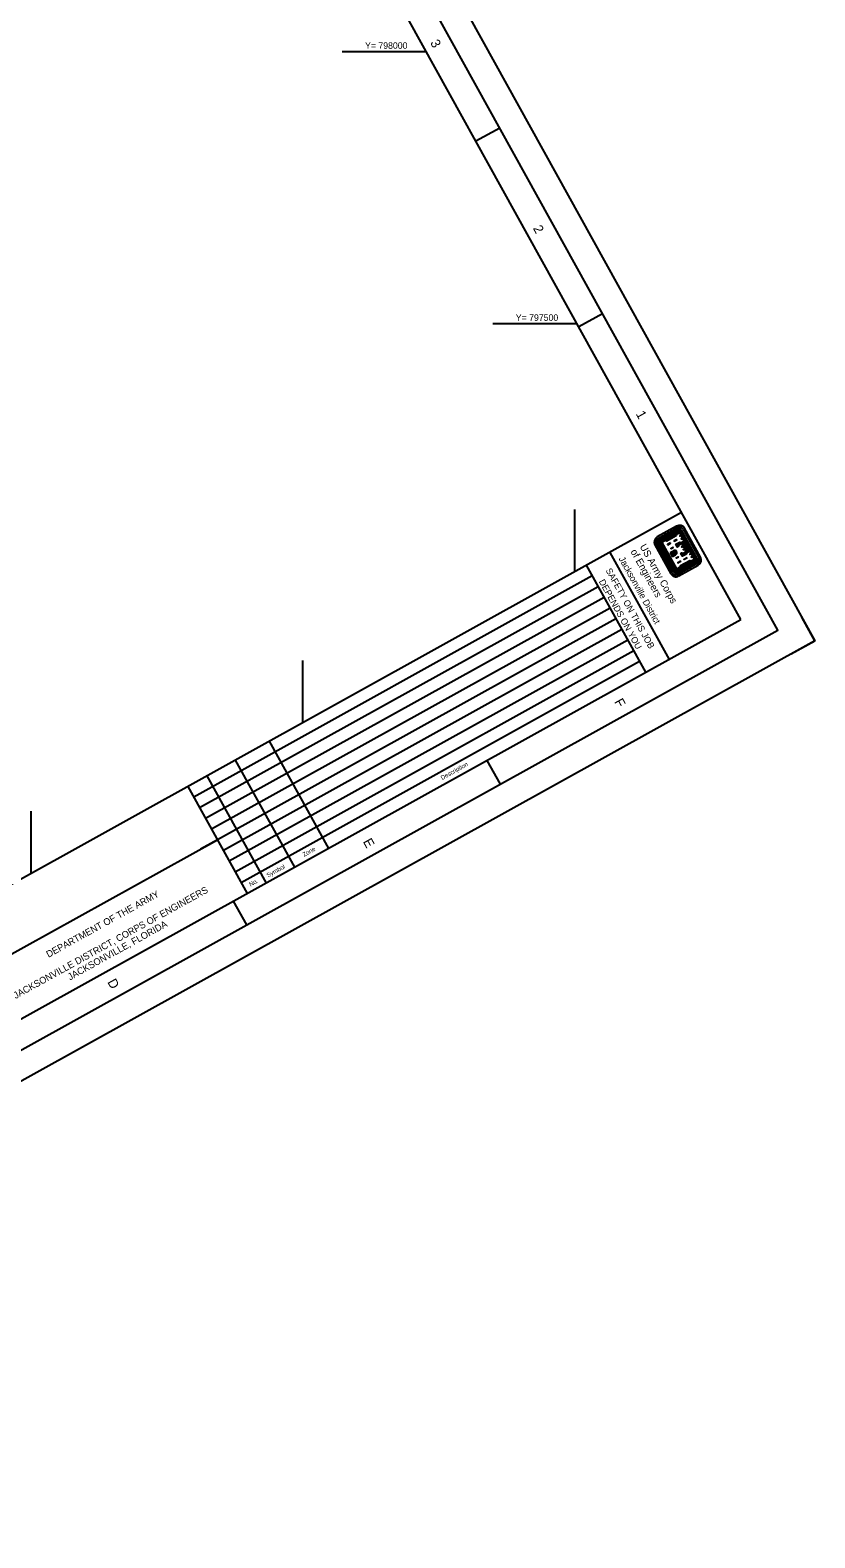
# Model space of a CAD drawing. Extents: x 602834 to 607941, y 795268 to 800765.
# Drawn here: x 606498 to 607941, y 795269 to 798039 of the extents above; entities that cross this region are included whole.
import ezdxf

# ---------------------------------------------------------------- set-up
doc = ezdxf.new("R2010")
doc.units = 0
for name, color, linetype in [('G-ANNO-NPLT', 7, 'Continuous'), ('G-ANNO-TEXT-LOGO', 7, 'Continuous'), ('G-ANNO-TEXT-TTLB', 7, 'Continuous'), ('G-ANNO-TTLB', 7, 'Continuous'), ('V-TOPO-COOR-STAT', 7, 'Continuous')]:
    doc.layers.add(name, color=color, linetype=linetype)

msp = doc.modelspace()

# ---------------------------------------------------------------- linework, layer by layer
at = {"layer": 'G-ANNO-NPLT'}
msp.add_lwpolyline([(605807.9, 800765.3), (607941.3, 796917.1), (604967.7, 795268.6), (602834.3, 799116.7)], close=True, dxfattribs=at)
msp.add_lwpolyline([(607897.6, 796892.9), (607941.3, 796917.1), (607917.1, 796960.8)], dxfattribs=at)
at = {"layer": 'G-ANNO-TEXT-LOGO'}
for p, q in [((607687.1, 797127.9), (607651.2, 797108.1)), ((607652.8, 797105.3), (607688.7, 797125.1)), ((607690.4, 797122.1), (607654.5, 797102.2)), ((607690.8, 797121.3), (607654.9, 797101.4)), ((607691.2, 797120.6), (607655.3, 797100.7)), ((607691.6, 797119.8), (607655.8, 797099.9)), ((607692.1, 797119), (607656.2, 797099.1)), ((607692.5, 797118.2), (607656.9, 797098.5)), ((607692.9, 797117.5), (607658.1, 797098.2)), ((607685.6, 797112.7), (607667.2, 797102.5)), ((607685.3, 797111.5), (607668.6, 797102.2)), ((607722.3, 797065.7), (607692.8, 797118.9)), ((607723.1, 797066.1), (607693.6, 797119.3)), ((607723.8, 797066.5), (607694.3, 797119.7)), ((607724.6, 797067), (607695.1, 797120.1)), ((607725.4, 797067.4), (607695.9, 797120.6)), ((607698.9, 797122.2), (607728.3, 797069.1)), ((607731.1, 797070.6), (607701.7, 797123.8)), ((607647, 797093.5), (607676.5, 797040.3)), ((607679.4, 797041.9), (607649.9, 797095.1)), ((607682.4, 797043.6), (607652.9, 797096.8)), ((607683.1, 797044), (607653.6, 797097.2)), ((607683.9, 797044.4), (607654.4, 797097.6)), ((607684.7, 797044.9), (607655.2, 797098)), ((607685.4, 797045.2), (607655.9, 797098.4)), ((607686, 797046), (607656.9, 797098.5)), ((607686.4, 797047.2), (607658.1, 797098.2)), ((607697.8, 797097.5), (607706.8, 797081.3)), ((607698.6, 797098), (607707.6, 797081.7)), ((607699.3, 797098.3), (607708.3, 797082.1)), ((607700.1, 797098.8), (607709.1, 797082.5)), ((607700.9, 797099.2), (607709.9, 797082.9)), ((607701.6, 797099.6), (607710.6, 797083.3)), ((607702.3, 797100), (607711.4, 797083.8)), ((607675.4, 797079.1), (607681.3, 797082.3)), ((607675.4, 797079.1), (607679.3, 797072.1)), ((607675.8, 797078.4), (607681.7, 797081.6)), ((607676.3, 797077.6), (607682.1, 797080.8)), ((607676.7, 797076.8), (607682.6, 797080)), ((607677.1, 797076.1), (607683, 797079.3)), ((607677.7, 797075), (607683.5, 797078.3)), ((607678.1, 797074.3), (607683.9, 797077.6)), ((607678.5, 797073.6), (607684.4, 797076.8)), ((607678.9, 797072.8), (607684.8, 797076)), ((607679.3, 797072.1), (607685.2, 797075.3)), ((607721.6, 797065.8), (607686, 797046)), ((607722, 797065), (607686.2, 797045.1)), ((607721.2, 797066.5), (607686.4, 797047.2)), ((607722.5, 797064.2), (607686.6, 797044.3)), ((607722.8, 797063.5), (607687, 797043.6)), ((607723.3, 797062.7), (607687.4, 797042.8)), ((607723.7, 797061.9), (607687.9, 797042)), ((607725.4, 797058.9), (607689.5, 797039.1)), ((607691.1, 797036.2), (607727, 797056.1)), ((607713.2, 797062.8), (607695, 797052.7)), ((607712, 797063.2), (607695.3, 797053.9))]:
    msp.add_line(p, q, dxfattribs=at)
for points in [[(607693.2, 797116.9), (607686.3, 797113.1), (607685.6, 797110.8), (607668.9, 797101.5), (607666.5, 797102.1), (607658.9, 797097.9), (607686.6, 797048.1), (607694.2, 797052.3), (607694.9, 797054.7), (607711.6, 797064), (607713.9, 797063.2), (607720.9, 797067.1), (607717.2, 797073.6), (607714.4, 797078.7), (607711.8, 797083.4), (607704.9, 797079.6), (607704.3, 797077.1), (607698.2, 797073.7), (607696.2, 797077.4), (607696.8, 797077.7), (607699.2, 797077), (607706, 797080.8), (607702.4, 797087.4), (607699.6, 797092.4), (607697, 797097.1), (607690.2, 797093.3), (607689.5, 797090.9), (607688.9, 797090.5), (607686.8, 797094.2), (607693, 797097.6), (607695.3, 797096.8), (607702.2, 797100.7), (607698.6, 797107.2), (607695.8, 797112.3), (607693.2, 797116.9)], [(607692.8, 797115.8), (607687, 797112.6), (607686.3, 797110.1), (607669, 797100.5), (607666.6, 797101.2), (607660.1, 797097.7), (607687, 797049.2), (607693.4, 797052.8), (607694.1, 797055.3), (607711.4, 797064.9), (607713.9, 797064.1), (607719.7, 797067.3), (607717.1, 797072.1), (607714.3, 797070.6), (607714.1, 797071), (607716.8, 797072.5), (607714.2, 797077.1), (607711.5, 797075.6), (607711.3, 797076), (607714.1, 797077.5), (607711.4, 797082.2), (607705.7, 797079), (607705, 797076.6), (607697.9, 797072.6), (607695.1, 797077.7), (607696.7, 797078.6), (607699.2, 797077.9), (607704.9, 797081.1), (607702.3, 797085.8), (607699.6, 797084.3), (607699.4, 797084.7), (607702.1, 797086.2), (607699.5, 797090.9), (607696.8, 797089.4), (607696.6, 797089.9), (607699.3, 797091.4), (607696.7, 797096), (607690.9, 797092.8), (607690.2, 797090.3), (607688.6, 797089.4), (607685.8, 797094.5), (607692.8, 797098.4), (607695.3, 797097.7), (607701.1, 797100.9), (607698.5, 797105.6), (607695.8, 797104.1), (607695.5, 797104.5), (607698.2, 797106), (607695.6, 797110.7), (607692.9, 797109.2), (607692.7, 797109.6), (607695.4, 797111.1), (607692.8, 797115.8)], [(607675.8, 797097), (607670.6, 797094.1), (607670.9, 797093.6), (607676.1, 797096.5), (607675.8, 797097)], [(607680.3, 797088.9), (607676.7, 797086.9), (607676.9, 797086.5), (607680.5, 797088.5), (607680.3, 797088.9)], [(607687.4, 797103.4), (607682.4, 797100.6), (607682.7, 797100.1), (607687.7, 797102.9), (607687.4, 797103.4)], [(607693.7, 797096.4), (607693.1, 797096.6), (607688.1, 797093.8), (607689, 797092.2), (607689.5, 797093.9), (607693.9, 797096.4)], [(607690.3, 797070.9), (607686.7, 797068.9), (607686.4, 797069.4), (607690, 797071.4), (607690.3, 797070.9)], [(607694.7, 797063), (607689.5, 797060.1), (607689.3, 797060.5), (607694.4, 797063.4), (607694.7, 797063)], [(607703.7, 797078.4), (607703.5, 797077.7), (607698.5, 797074.9), (607697.7, 797076.5), (607699.4, 797076.1), (607703.8, 797078.5)], [(607706.3, 797069.4), (607701.2, 797066.6), (607701, 797067), (607706.1, 797069.8), (607706.3, 797069.4)]]:
    msp.add_lwpolyline(points, dxfattribs=at)
for centre, major_axis, start_param, end_param in [((607692.3, 797118.6), (5.19, -9.37), 1.57078, 3.141576), ((607692.3, 797118.6), (3.63, -6.55), 1.57078, 3.141576), ((607692.3, 797118.6), (1.95, -3.51), 1.57078, 3.141576), ((607692.3, 797118.6), (1.53, -2.75), 1.57078, 3.141576), ((607692.3, 797118.6), (1.11, -2), 1.57078, 3.141576), ((607692.3, 797118.6), (0.69, -1.24), 1.57078, 3.141576), ((607692.3, 797118.6), (0.265, -0.477), 1.57078, 3.141576), ((607656.4, 797098.7), (-5.19, 9.37), 6.28317, 7.853966), ((607656.4, 797098.7), (-3.63, 6.55), 6.28317, 7.853966), ((607656.4, 797098.7), (-1.95, 3.51), 6.28317, 7.853966), ((607656.4, 797098.7), (-1.53, 2.75), 6.28317, 7.853966), ((607656.4, 797098.7), (-1.11, 2), 6.28317, 7.853966), ((607656.4, 797098.7), (-0.69, 1.24), 6.28317, 7.853966), ((607656.4, 797098.7), (-0.265, 0.477), 6.28317, 7.853966), ((607683.6, 797077.3), (-2.69, 4.86), 4.985832, 6.214359), ((607683.6, 797077.3), (-2.27, 4.1), 4.947465, 6.21436), ((607683.6, 797077.3), (-1.85, 3.34), 4.947465, 6.21436), ((607683.6, 797077.3), (-1.43, 2.58), 4.947465, 6.21436), ((607683.6, 797077.3), (-1.01, 1.82), 4.947465, 6.214359), ((607682.1, 797079.9), (1.01, -1.82), 0.068794, 1.335689), ((607682.1, 797079.9), (1.43, -2.58), 0.068794, 1.335689), ((607682.1, 797079.9), (1.85, -3.34), 0.068795, 1.335689), ((607682.1, 797079.9), (2.27, -4.1), 0.068795, 1.335689), ((607682.1, 797079.9), (2.69, -4.86), 0.068795, 1.29842), ((607721.8, 797065.5), (0.265, -0.477), 6.283169, 7.853965), ((607721.8, 797065.5), (0.69, -1.24), 6.283169, 7.853965), ((607721.8, 797065.5), (1.11, -2), 6.283169, 7.853965), ((607721.8, 797065.5), (1.53, -2.75), 6.283169, 7.853965), ((607721.8, 797065.5), (1.95, -3.51), 6.283169, 7.853965), ((607721.8, 797065.5), (3.63, -6.55), 6.28317, 7.853966), ((607721.8, 797065.5), (5.19, -9.37), 6.283169, 7.853965), ((607685.9, 797045.6), (5.19, -9.37), 4.712373, 6.28317), ((607685.9, 797045.6), (-3.63, 6.55), 1.570781, 3.141577), ((607685.9, 797045.6), (1.95, -3.51), 4.712373, 6.28317), ((607685.9, 797045.6), (1.53, -2.75), 4.712373, 6.28317), ((607685.9, 797045.6), (1.11, -2), 4.712373, 6.28317), ((607685.9, 797045.6), (0.69, -1.24), 4.712373, 6.28317), ((607685.9, 797045.6), (0.265, -0.477), 4.712373, 6.28317)]:
    msp.add_ellipse(centre, major_axis=major_axis, ratio=0.99964, start_param=start_param, end_param=end_param, dxfattribs=at)
at = {"layer": 'G-ANNO-TTLB'}
for p, q in [((607361.8, 797859.3), (607318.1, 797835)), ((607550.9, 797518.2), (607507.2, 797494)), ((607696.2, 797152.9), (604897.6, 795601.3)), ((607520.7, 797056.3), (607629.8, 796859.5)), ((607564, 797079.5), (607673.1, 796882.8)), ((607531.8, 797036.2), (606799, 796629.9)), ((607542.8, 797016.5), (606809.9, 796610.3)), ((607553.7, 796996.9), (606820.8, 796590.6)), ((607564.6, 796977.2), (606831.7, 796570.9)), ((607575.5, 796957.5), (606842.7, 796551.2)), ((607586.4, 796937.8), (606853.6, 796531.5)), ((607597.3, 796918.1), (606864.5, 796511.9)), ((607608.2, 796898.5), (606875.4, 796492.2)), ((607619.1, 796878.8), (606886.3, 796472.5)), ((606937.8, 796732.4), (607046.9, 796535.6)), ((606875.5, 796697.9), (606984.6, 796501.1)), ((607363, 796653.7), (607338.8, 796697.4)), ((606823.1, 796668.8), (606932.1, 796472)), ((606788.2, 796649.4), (606897.3, 796452.7)), ((606090.7, 796134.9), (606842.7, 796551.1)), ((606842.7, 796551.1), (606811.8, 796533.9)), ((606896.6, 796395.1), (606872.3, 796438.8))]:
    msp.add_line(p, q, dxfattribs=at)
for points in [[(602902.3, 799097.2), (604987.2, 795336.5), (607873.3, 796936.6), (605788.4, 800697.3)], [(607805.4, 796956.1), (605805.3, 800563.7), (603006.6, 799012.2), (605006.7, 795404.5)]]:
    msp.add_lwpolyline(points, close=True, dxfattribs=at)
at = {"layer": 'V-TOPO-COOR-STAT'}
for p, q in [((607072.3, 798000), (607226.6, 798000)), ((607349.4, 797500), (607503.8, 797500)), ((607500, 797044.1), (607500, 797158.4)), ((607000, 796766.9), (607000, 796881.2)), ((606500, 796489.7), (606500, 796604))]:
    msp.add_line(p, q, dxfattribs=at)

# ---------------------------------------------------------------- texts
at = {"layer": 'G-ANNO-TEXT-TTLB'}
for s, height, rotation, p in [('of Engineers', 13.086, 299.0039, (607601.8, 797081.1)), ('US Army Corps', 13.086, 299.0039, (607618.8, 797090.5)), ('Jacksonville District', 11.9, 299.0039, (607580.2, 797068)), ('DEPENDS ON YOU', 11.9, 299.0039, (607543.6, 797026.1)), ('SAFETY ON THIS JOB', 11.9, 299.0039, (607556.2, 797046.5)), ('Description', 8, 29.0039, (607256, 796661.1)), ('Zone', 8, 29.0039, (607001.8, 796519.9)), ('Symbol', 8, 29.0039, (606935.7, 796481.8)), ('No.', 8, 29.0039, (606903.6, 796465.2)), ('JACKSONVILLE DISTRICT, CORPS OF ENGINEERS', 12.5, 29.0039, (606471.8, 796258.7)), ('DEPARTMENT OF THE ARMY', 12.5, 29.0039, (606532.1, 796334.4)), ('JACKSONVILLE, FLORIDA', 12.5, 29.0039, (606571.6, 796292.8))]:
    msp.add_text(s, height=height, rotation=rotation, dxfattribs=at).set_placement(p)
at = {"layer": 'G-ANNO-TTLB'}
for s, p in [('3', (607233.4, 798016.3)), ('2', (607422.5, 797675.2)), ('1', (607611.6, 797334.1)), ('F', (607571.9, 796805.2)), ('E', (607109.8, 796548.1)), ('D', (606639.8, 796290.1))]:
    msp.add_text(s, height=17.5, rotation=299.0039, dxfattribs=at).set_placement(p)
at = {"layer": 'V-TOPO-COOR-STAT'}
for s, p in [('Y= 798000', (607114.1, 798005)), ('Y= 797500', (607391.3, 797505))]:
    msp.add_text(s, height=12, dxfattribs=at).set_placement(p)

doc.saveas('drawing.dxf')
